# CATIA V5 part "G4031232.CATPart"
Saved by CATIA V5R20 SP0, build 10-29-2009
Part number: G4031232
Revision: 8
Definition: design
Nomenclature: G4031232
Source: made
Description: NOT SPECIFIED
Bounding box of the stored display mesh (mm): x -16 to 16, y -10.833 to 10.833, z -11 to 11
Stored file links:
  C:\Users\Raffaele\Desktop\3D X SITO CF\BOLEX\27-BUSH REF 403\G4031232.CATPart
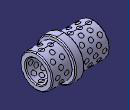
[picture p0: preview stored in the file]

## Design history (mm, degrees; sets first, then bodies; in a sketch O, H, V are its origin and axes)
Body1 "MANIFOLD_SOLID_BREP #8487" (main body)
  Solid1: solid without history
Body2 "MANIFOLD_SOLID_BREP #8630"
  Solid2: solid without history
Body3 "MANIFOLD_SOLID_BREP #8773"
  Solid3: solid without history
Body4 "MANIFOLD_SOLID_BREP #8916"
  Solid4: solid without history
Body5 "MANIFOLD_SOLID_BREP #9059"
  Solid5: solid without history
Body6 "MANIFOLD_SOLID_BREP #9204"
  Solid6: solid without history
Body7 "MANIFOLD_SOLID_BREP #9349"
  Solid7: solid without history
Body8 "MANIFOLD_SOLID_BREP #9494"
  Solid8: solid without history
Body9 "MANIFOLD_SOLID_BREP #9639"
  Solid9: solid without history
Body10 "MANIFOLD_SOLID_BREP #9782"
  Solid10: solid without history
Body11 "MANIFOLD_SOLID_BREP #9925"
  Solid11: solid without history
Body12 "MANIFOLD_SOLID_BREP #10070"
  Solid12: solid without history
Body13 "MANIFOLD_SOLID_BREP #10215"
  Solid13: solid without history
Body14 "MANIFOLD_SOLID_BREP #10360"
  Solid14: solid without history
Body15 "MANIFOLD_SOLID_BREP #10505"
  Solid15: solid without history
Body16 "MANIFOLD_SOLID_BREP #10648"
  Solid16: solid without history
Body17 "MANIFOLD_SOLID_BREP #10791"
  Solid17: solid without history
Body18 "MANIFOLD_SOLID_BREP #10936"
  Solid18: solid without history
Body19 "MANIFOLD_SOLID_BREP #11081"
  Solid19: solid without history
Body20 "MANIFOLD_SOLID_BREP #11226"
  Solid20: solid without history
Body21 "MANIFOLD_SOLID_BREP #11371"
  Solid21: solid without history
Body22 "MANIFOLD_SOLID_BREP #11516"
  Solid22: solid without history
Body23 "MANIFOLD_SOLID_BREP #11661"
  Solid23: solid without history
Body24 "MANIFOLD_SOLID_BREP #11806"
  Solid24: solid without history
Body25 "MANIFOLD_SOLID_BREP #11951"
  Solid25: solid without history
Body26 "MANIFOLD_SOLID_BREP #12096"
  Solid26: solid without history
Body27 "MANIFOLD_SOLID_BREP #12241"
  Solid27: solid without history
Body28 "MANIFOLD_SOLID_BREP #12386"
  Solid28: solid without history
Body29 "MANIFOLD_SOLID_BREP #12531"
  Solid29: solid without history
Body30 "MANIFOLD_SOLID_BREP #12674"
  Solid30: solid without history
Body31 "MANIFOLD_SOLID_BREP #12819"
  Solid31: solid without history
Body32 "MANIFOLD_SOLID_BREP #12964"
  Solid32: solid without history
Body33 "MANIFOLD_SOLID_BREP #13107"
  Solid33: solid without history
Body34 "MANIFOLD_SOLID_BREP #13250"
  Solid34: solid without history
Body35 "MANIFOLD_SOLID_BREP #13393"
  Solid35: solid without history
Body36 "MANIFOLD_SOLID_BREP #13538"
  Solid36: solid without history
Body37 "MANIFOLD_SOLID_BREP #13683"
  Solid37: solid without history
Body38 "MANIFOLD_SOLID_BREP #13828"
  Solid38: solid without history
Body39 "MANIFOLD_SOLID_BREP #13973"
  Solid39: solid without history
Body40 "MANIFOLD_SOLID_BREP #14116"
  Solid40: solid without history
Body41 "MANIFOLD_SOLID_BREP #14259"
  Solid41: solid without history
Body42 "MANIFOLD_SOLID_BREP #14404"
  Solid42: solid without history
Body43 "MANIFOLD_SOLID_BREP #14549"
  Solid43: solid without history
Body44 "MANIFOLD_SOLID_BREP #14694"
  Solid44: solid without history
Body45 "MANIFOLD_SOLID_BREP #14839"
  Solid45: solid without history
Body46 "MANIFOLD_SOLID_BREP #14982"
  Solid46: solid without history
Body47 "MANIFOLD_SOLID_BREP #15125"
  Solid47: solid without history
Body48 "MANIFOLD_SOLID_BREP #15270"
  Solid48: solid without history
Body49 "MANIFOLD_SOLID_BREP #15415"
  Solid49: solid without history
Body50 "MANIFOLD_SOLID_BREP #15560"
  Solid50: solid without history
Body51 "MANIFOLD_SOLID_BREP #15705"
  Solid51: solid without history
Body52 "MANIFOLD_SOLID_BREP #15850"
  Solid52: solid without history
Body53 "MANIFOLD_SOLID_BREP #15995"
  Solid53: solid without history
Body54 "MANIFOLD_SOLID_BREP #16140"
  Solid54: solid without history
Body55 "MANIFOLD_SOLID_BREP #16283"
  Solid55: solid without history
Body56 "MANIFOLD_SOLID_BREP #16426"
  Solid56: solid without history
Body57 "MANIFOLD_SOLID_BREP #16569"
  Solid57: solid without history
Body58 "MANIFOLD_SOLID_BREP #16712"
  Solid58: solid without history
Body59 "MANIFOLD_SOLID_BREP #16857"
  Solid59: solid without history
Body60 "MANIFOLD_SOLID_BREP #17002"
  Solid60: solid without history
Body61 "MANIFOLD_SOLID_BREP #17147"
  Solid61: solid without history
Body62 "MANIFOLD_SOLID_BREP #17292"
  Solid62: solid without history
Body63 "MANIFOLD_SOLID_BREP #17437"
  Solid63: solid without history
Body64 "MANIFOLD_SOLID_BREP #17582"
  Solid64: solid without history
Body65 "MANIFOLD_SOLID_BREP #17727"
  Solid65: solid without history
